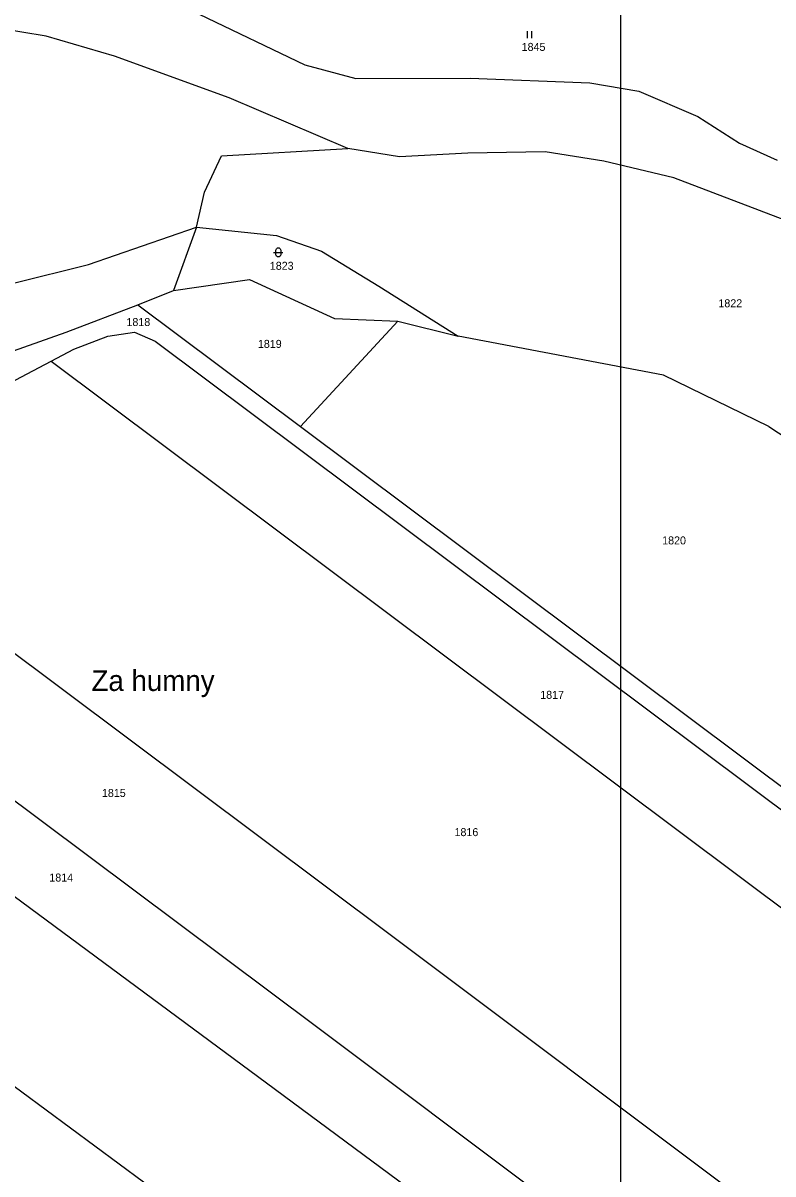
# Model space of a CAD drawing. Extents: x -802857 to -799647, y -1020285 to -1015884.
# Drawn here: x -801830.8 to -801671.4, y -1017493.5 to -1017248.9 of the extents above; entities that cross this region are included whole.
import ezdxf

# ---------------------------------------------------------------- set-up
doc = ezdxf.new("R2010")
doc.units = 0
for name, color, linetype in [('Default', 7, 'Continuous'), ('KN_HRANICE', 7, 'Continuous'), ('KN_KULTURY', 7, 'Continuous'), ('KN_PARCELY', 7, 'Continuous'), ('LEGENDA', 7, 'Continuous')]:
    doc.layers.add(name, color=color, linetype=linetype)

# ---------------------------------------------------------------- blocks, each defined once
blk = doc.blocks.new('306')
at = {"layer": 'Default'}
for p, q in [((-0.5, 1.5), (-0.5, 0)), ((0.5, 0), (0.5, 1.5))]:
    blk.add_line(p, q, dxfattribs=at)
blk = doc.blocks.new('316')
at = {"layer": 'Default'}
for points in [[(-1, 1), (0.27, 1), (1, 1)], [(-0.5, 1.5), (-0.4, 1.79), (-0.15, 1.97), (0.16, 1.97), (0.41, 1.79), (0.51, 1.5), (0.51, 0.5), (0.41, 0.21), (0.16, 0.03), (-0.15, 0.03), (-0.4, 0.21), (-0.5, 0.5), (-0.5, 1.5)]]:
    blk.add_lwpolyline(points, dxfattribs=at)

msp = doc.modelspace()

# ---------------------------------------------------------------- linework, layer by layer
at = {"layer": 'KN_HRANICE'}
for p, q in [((-801793.4, -1017247.04), (-801770.93, -1017257.82)), ((-801825.91, -1017251.69), (-801837.36, -1017249.87)), ((-801811.34, -1017255.97), (-801825.91, -1017251.69)), ((-801787.01, -1017264.79), (-801811.34, -1017255.97)), ((-801770.93, -1017257.82), (-801760.04, -1017260.74)), ((-801760.04, -1017260.74), (-801735.74, -1017260.62)), ((-801735.74, -1017260.62), (-801710.32, -1017261.66)), ((-801710.32, -1017261.66), (-801699.91, -1017263.42)), ((-801761.76, -1017275.57), (-801787.01, -1017264.79)), ((-801699.91, -1017263.42), (-801687.36, -1017268.82)), ((-801687.36, -1017268.82), (-801678.51, -1017274.48)), ((-801678.51, -1017274.48), (-801670.52, -1017278.09)), ((-801792.26, -1017284.84), (-801788.6, -1017277.18)), ((-801788.6, -1017277.18), (-801761.76, -1017275.57)), ((-801750.82, -1017277.33), (-801761.76, -1017275.57)), ((-801736.26, -1017276.56), (-801750.82, -1017277.33)), ((-801719.86, -1017276.29), (-801736.26, -1017276.56)), ((-801707.38, -1017278.31), (-801719.86, -1017276.29)), ((-801692.48, -1017281.81), (-801707.38, -1017278.31)), ((-801658.95, -1017294.66), (-801692.48, -1017281.81)), ((-801793.91, -1017292.28), (-801792.26, -1017284.84)), ((-801816.89, -1017300.2), (-801793.91, -1017292.28)), ((-801793.91, -1017292.28), (-801798.84, -1017305.74)), ((-801793.91, -1017292.28), (-801776.93, -1017294.07)), ((-801776.93, -1017294.07), (-801767.36, -1017297.41)), ((-801767.36, -1017297.41), (-801755.22, -1017304.85)), ((-801832.86, -1017304.19), (-801816.89, -1017300.2)), ((-801798.84, -1017305.74), (-801782.7, -1017303.4)), ((-801782.7, -1017303.4), (-801764.64, -1017311.74)), ((-801806.42, -1017308.77), (-801798.84, -1017305.74)), ((-801755.22, -1017304.85), (-801738.31, -1017315.47)), ((-801821.66, -1017314.59), (-801806.42, -1017308.77)), ((-801806.42, -1017308.77), (-801771.82, -1017334.66)), ((-801764.64, -1017311.74), (-801751.14, -1017312.3)), ((-801771.82, -1017334.66), (-801751.14, -1017312.3)), ((-801751.14, -1017312.3), (-801738.31, -1017315.47)), ((-801844.56, -1017322.69), (-801821.66, -1017314.59)), ((-801820.01, -1017318.24), (-801812.8, -1017315.49)), ((-801812.8, -1017315.49), (-801807.12, -1017314.59)), ((-801807.12, -1017314.59), (-801802.71, -1017316.54)), ((-801802.71, -1017316.54), (-801653.38, -1017428.3)), ((-801694.67, -1017323.74), (-801738.31, -1017315.47)), ((-801824.8, -1017320.76), (-801820.01, -1017318.24)), ((-801841.82, -1017329.72), (-801824.8, -1017320.76)), ((-801824.8, -1017320.76), (-801717.22, -1017401.3)), ((-801672.29, -1017334.66), (-801694.67, -1017323.74)), ((-801901.1, -1017331.64), (-801752.52, -1017442.84)), ((-801771.82, -1017334.66), (-801650.93, -1017425.14)), ((-801672.29, -1017334.66), (-801607.17, -1017377.34)), ((-801926.87, -1017343.6), (-801768.75, -1017461.94)), ((-801935.26, -1017358.65), (-801779.08, -1017474.09)), ((-801941.53, -1017394.58), (-801799.52, -1017499.3)), ((-801717.22, -1017401.3), (-801595.69, -1017492.25)), ((-801752.52, -1017442.84), (-801623.34, -1017539.52)), ((-801768.75, -1017461.94), (-801697.3, -1017515.42)), ((-801779.08, -1017474.09), (-801707.48, -1017527.01))]:
    msp.add_line(p, q, dxfattribs=at)
at = {"layer": 'LEGENDA'}
msp.add_lwpolyline([(-801703.84, -1017613.71), (-800862.84, -1017613.71), (-800862.84, -1017019.71), (-801703.84, -1017019.71)], close=True, dxfattribs=at)

# ---------------------------------------------------------------- block references
at = {"layer": 'KN_KULTURY'}
for name, p in [('306', (-801723.13, -1017252.15)), ('316', (-801776.56, -1017298.66))]:
    msp.add_blockref(name, p, dxfattribs=at)

# ---------------------------------------------------------------- texts
at = {"layer": 'KN_PARCELY'}
for s, height, p in [('1845', 1.7, (-801724.83, -1017254.85)), ('1823', 1.7, (-801778.36, -1017301.36)), ('1822', 1.7, (-801683.01, -1017309.32)), ('1818', 1.7, (-801808.83, -1017313.31)), ('1819', 1.7, (-801780.89, -1017317.95)), ('1820', 1.7, (-801694.96, -1017359.71)), ('Za humny', 4.4, (-801816.26, -1017390.85)), ('1817', 1.7, (-801720.88, -1017392.52)), ('1815', 1.7, (-801814.04, -1017413.37)), ('1816', 1.7, (-801739.1, -1017421.69)), ('1814', 1.7, (-801825.22, -1017431.34))]:
    msp.add_text(s, height=height, dxfattribs=at).set_placement(p)

doc.saveas('drawing.dxf')
